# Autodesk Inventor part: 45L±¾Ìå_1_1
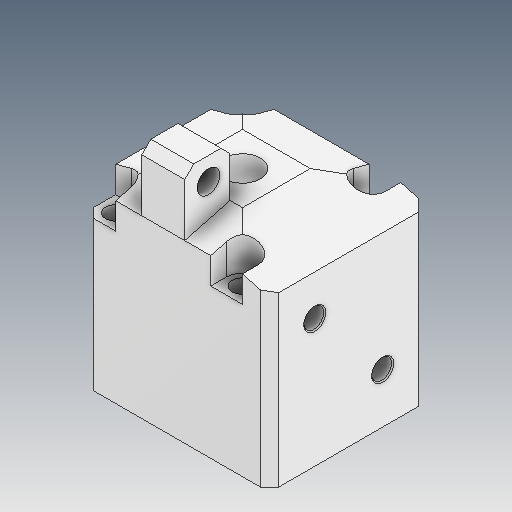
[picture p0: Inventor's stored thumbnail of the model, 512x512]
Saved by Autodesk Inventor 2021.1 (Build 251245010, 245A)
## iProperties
Created: 2021-05
Part Number: 45L±¾Ìå_1_1
Material: Ogólny
Document SubType Name: Modeling
Designer: user
Density: 1 g/cm^3
Appearance: Domyślna
Author: user
Revision Number: ÈÎºÎ
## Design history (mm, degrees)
feature "ÊäÈë1"
feature "ÊäÈë2"
node "Bryła1"
node "Bryła2"
